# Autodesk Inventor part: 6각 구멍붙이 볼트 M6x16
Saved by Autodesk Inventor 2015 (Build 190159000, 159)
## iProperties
Created: 2026-07
Part Number: 6각 구멍붙이 볼트 M6x16
Material: 일반
Document SubType Name: Modeling
Designer: USER
Density: 1 g/cm^3
Appearance: 기본값
Author: USER
Author: jhkim
Creation Date: 2026-07-01
Sending System: Autodesk Inventor 2027
Preprocessor: ST-DEVELOPER v20.1
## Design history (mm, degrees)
node "6각 구멍붙이 볼트 M6x161"
body "Solid1"
node "기준1"
